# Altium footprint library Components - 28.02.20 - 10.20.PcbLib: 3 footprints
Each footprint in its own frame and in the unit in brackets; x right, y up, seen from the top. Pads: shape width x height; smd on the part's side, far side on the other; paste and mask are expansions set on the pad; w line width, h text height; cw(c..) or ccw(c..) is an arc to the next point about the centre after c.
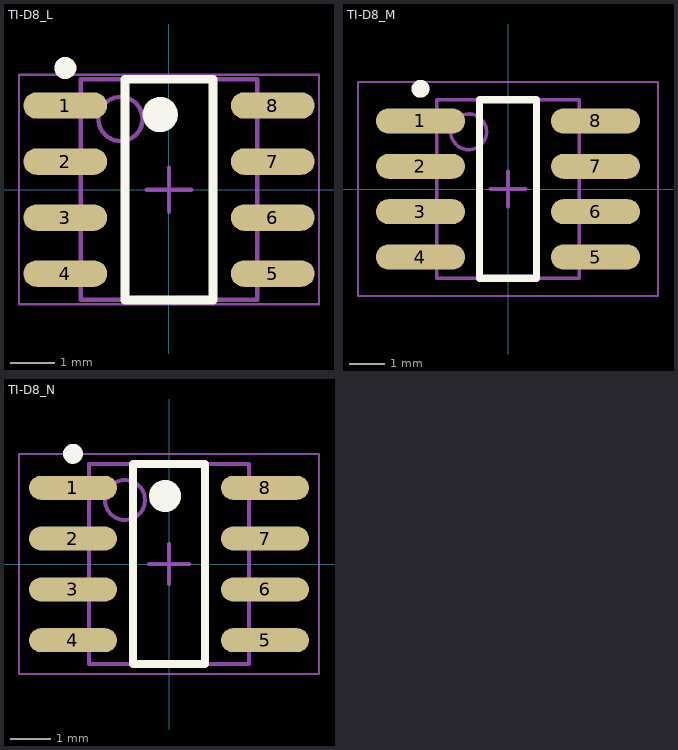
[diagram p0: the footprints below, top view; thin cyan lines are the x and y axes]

## TI-D8_L [mm] "SOIC, 8-Leads, Body 5x4mm, Pitch 1.27mm, IPC High Density"
height 1.75
pads (8):
  oval 1.9x0.6 smd: 1(-2.35,1.905) 2(-2.35,0.635) 3(-2.35,-0.635) 4(-2.35,-1.905) 5(2.35,-1.905) 6(2.35,-0.635) 7(2.35,0.635) 8(2.35,1.905)
Top Overlay:
  circle w0.4: c-0.2,1.7 r0.2
  circle w0.25: c-2.35,2.755 r0.125
  lines w0.2: -1,-2.5 1,-2.5 1,2.5 -1,2.5 -1,-2.5
Mechanical 13:
  circle w0.1: c-1.1,1.6 r0.5
  lines w0.1: -2,-2.5 2,-2.5 2,2.5 -2,2.5 -2,-2.5
Mechanical 15:
  lines w0.05: -3.4,-2.6 3.4,-2.6 3.4,2.6 -3.4,2.6 -3.4,-2.6
  lines w0.1: -0.5,0 0.5,0 ; 0,-0.5 0,0.5
3D body: height 1.75, standoff 0.1, extent -2,-2.5 2,2.5

## TI-D8_M [mm] "SOIC, 8-Leads, Body 5x4mm, Pitch 1.27mm, IPC Low Density"
height 1.75
pads (8):
  oval 2.5x0.7 smd: 1(-2.45,1.905) 2(-2.45,0.635) 3(-2.45,-0.635) 4(-2.45,-1.905) 5(2.45,-1.905) 6(2.45,-0.635) 7(2.45,0.635) 8(2.45,1.905)
Top Overlay:
  circle w0.25: c-2.45,2.805 r0.125
  lines w0.2: -0.8,-2.5 -0.8,2.5 0.8,2.5 0.8,-2.5 -0.8,-2.5
Mechanical 13:
  circle w0.1: c-1.1,1.6 r0.5
  lines w0.1: -2,-2.5 -2,2.5 2,2.5 2,-2.5 -2,-2.5
Mechanical 15:
  lines w0.05: -4.2,-3 -4.2,3 4.2,3 4.2,-3 -4.2,-3
  lines w0.1: -0.5,0 0.5,0 ; 0,-0.5 0,0.5
3D body: height 1.75, standoff 0.1, extent -2,-2.5 2,2.5

## TI-D8_N [mm] "SOIC, 8-Leads, Body 5x4mm, Pitch 1.27mm, IPC Medium Density"
height 1.75
pads (8):
  oval 2.2x0.6 smd: 1(-2.4,1.905) 2(-2.4,0.635) 3(-2.4,-0.635) 4(-2.4,-1.905) 5(2.4,-1.905) 6(2.4,-0.635) 7(2.4,0.635) 8(2.4,1.905)
Top Overlay:
  circle w0.4: c-0.1,1.7 r0.2
  circle w0.25: c-2.4,2.755 r0.125
  lines w0.2: -0.9,-2.5 0.9,-2.5 0.9,2.5 -0.9,2.5 -0.9,-2.5
Mechanical 13:
  circle w0.1: c-1.1,1.6 r0.5
  lines w0.1: -2,-2.5 2,-2.5 2,2.5 -2,2.5 -2,-2.5
Mechanical 15:
  lines w0.05: -3.75,-2.75 3.75,-2.75 3.75,2.75 -3.75,2.75 -3.75,-2.75
  lines w0.1: -0.5,0 0.5,0 ; 0,-0.5 0,0.5
3D body: height 1.75, standoff 0.1, extent -2,-2.5 2,2.5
